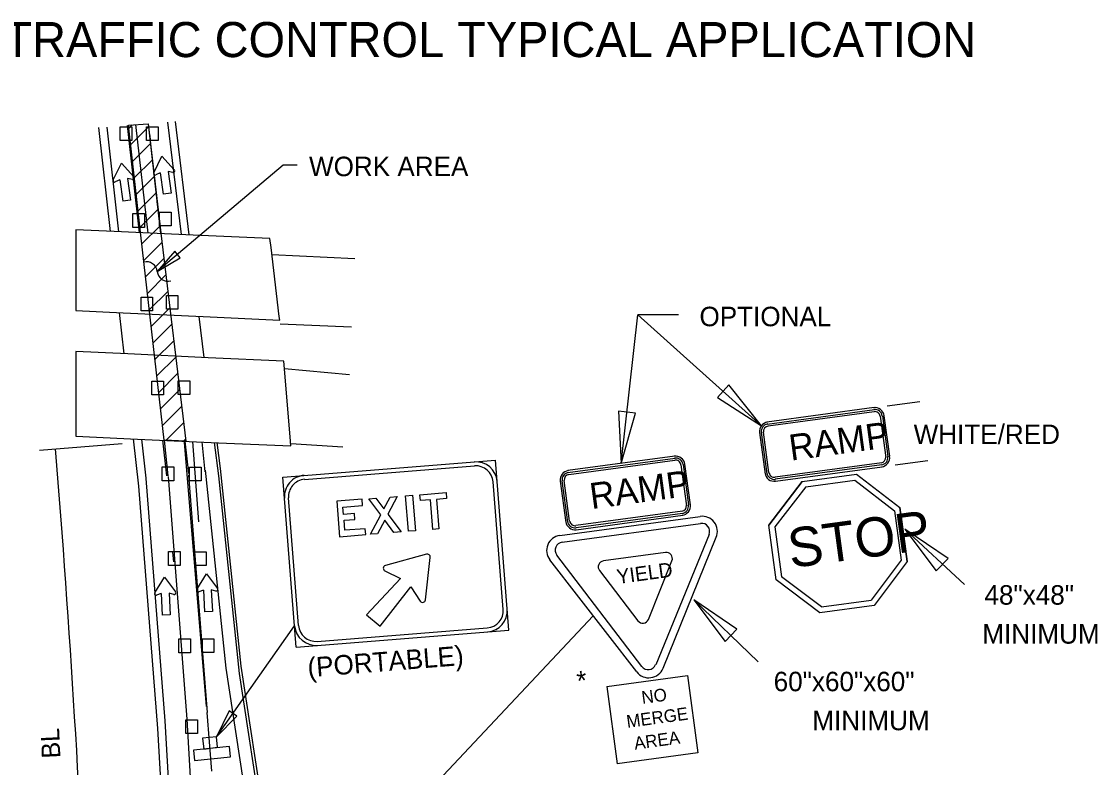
# Model space of a CAD drawing. Extents: x 612.48 to 619.85, y 611.03 to 621.01.
# Drawn here: x 615.025 to 618.336, y 618.714 to 621.01 of the extents above; entities that cross this region are included whole.
import ezdxf

# ---------------------------------------------------------------- set-up
doc = ezdxf.new("R2010")
doc.units = 0
for name, color, linetype in [('DETL-DIMS', 7, 'Continuous'), ('DETL-LINE', 7, 'Continuous'), ('DETL-NOTE', 7, 'Continuous'), ('DETL-TITL', 7, 'Continuous'), ('USER-BORD', 7, 'Continuous')]:
    doc.layers.add(name, color=color, linetype=linetype)

# ---------------------------------------------------------------- blocks, each defined once
blk = doc.blocks.new('SIGN14')
at = {"layer": 'USER-BORD'}
for points in [[(-0.0134, 0.0182), (0.011, 0.0189), (0.011, 0.0371), (-0.0134, 0.0371)], [(-0.0314, 0.0182), (-0.0314, 0), (0.032, 0), (0.032, 0.0182)]]:
    blk.add_lwpolyline(points, close=True, dxfattribs=at)

msp = doc.modelspace()

# ---------------------------------------------------------------- linework, layer by layer
at = {"layer": 'DETL-DIMS'}
for p, q in [((615.8309, 620.5677), (615.4432, 620.2404)), ((615.8738, 620.5677), (615.8309, 620.5677)), ((616.8708, 619.6502), (616.9221, 620.1071)), ((616.9221, 620.1071), (617.3017, 619.7661)), ((617.0473, 620.1071), (616.9221, 620.1071)), ((617.6888, 619.8271), (617.7898, 619.8408)), ((615.0807, 619.6909), (615.3347, 619.7115)), ((617.7134, 619.6453), (617.814, 619.659)), ((617.7434, 619.4477), (617.9271, 619.277)), ((617.0938, 619.2306), (617.2916, 619.0391)), ((615.9365, 618.2792), (616.7846, 619.1808)), ((615.6254, 618.8084), (615.8656, 619.1504))]:
    msp.add_line(p, q, dxfattribs=at)
for points in [[(615.514, 620.2825), (615.4966, 620.3032), (615.4431, 620.2403)], [(617.202, 619.8918), (617.1666, 619.8527), (617.3017, 619.7661)], [(616.9146, 619.8046), (616.8622, 619.8105), (616.8708, 619.6502)], [(617.8397, 619.3193), (617.8761, 619.3574), (617.7434, 619.4477)], [(617.1902, 619.1023), (617.2266, 619.1404), (617.0938, 619.2306)], [(615.688, 618.872), (615.6639, 618.8889), (615.6254, 618.8084)]]:
    msp.add_lwpolyline(points, close=True, dxfattribs=at)
for centre, radius, start, end in [((615.41, 620.2372), 0.0333, 5.7397, 105.25), ((615.4763, 620.2438), 0.0333, 185.7397, 285.25), ((573.0337, 616.2812), 42.2346, 2.39201, 4.63613)]:
    msp.add_arc(centre, radius, start, end, dxfattribs=at)
at = {"layer": 'DETL-LINE'}
for p, q in [((615.3541, 620.6908), (615.4151, 620.6956)), ((615.3551, 620.6813), (615.3655, 620.6917)), ((615.3609, 620.6305), (615.4162, 620.6858)), ((615.4151, 620.6956), (615.4543, 620.3593)), ((615.3667, 620.5797), (615.4221, 620.6352)), ((615.3077, 620.5232), (615.3328, 620.5739)), ((615.3328, 620.5739), (615.3707, 620.532)), ((615.3724, 620.5289), (615.428, 620.5845)), ((615.4324, 620.5448), (615.4574, 620.5956)), ((615.4574, 620.5956), (615.4954, 620.5536)), ((615.4522, 620.5447), (615.4386, 620.538)), ((615.4522, 620.5447), (615.4617, 620.4786)), ((615.4912, 620.5456), (615.4765, 620.5482)), ((615.4765, 620.5482), (615.4858, 620.4818)), ((615.3275, 620.5231), (615.314, 620.5164)), ((615.3275, 620.5231), (615.3369, 620.457)), ((615.3664, 620.524), (615.3518, 620.5266)), ((615.3518, 620.5266), (615.361, 620.4602)), ((615.3782, 620.4781), (615.4336, 620.5335)), ((615.384, 620.4273), (615.4399, 620.4832)), ((615.4858, 620.4818), (615.4617, 620.4786)), ((615.361, 620.4602), (615.3369, 620.457)), ((615.3897, 620.3765), (615.4458, 620.4325)), ((615.3955, 620.3257), (615.4517, 620.3818)), ((615.4544, 620.3587), (615.5306, 619.7183)), ((615.4013, 620.2749), (615.4577, 620.3313)), ((615.407, 620.2241), (615.4637, 620.2807)), ((615.4128, 620.1733), (615.4697, 620.2302)), ((615.4186, 620.1225), (615.4757, 620.1796)), ((615.3257, 620.1144), (615.34, 619.9875)), ((615.4243, 620.0717), (615.4817, 620.1291)), ((615.4301, 620.0209), (615.4877, 620.0785)), ((615.5712, 620.1026), (615.5867, 619.976)), ((615.4359, 619.9701), (615.4937, 620.0279)), ((615.4416, 619.9193), (615.4997, 619.9774)), ((615.4474, 619.8685), (615.5057, 619.9268)), ((615.4532, 619.8177), (615.5118, 619.8763)), ((615.4589, 619.7669), (615.5178, 619.8257)), ((617.6488, 619.8217), (617.319, 619.7769)), ((617.32, 619.7712), (617.6496, 619.8159)), ((617.3224, 619.7653), (617.6487, 619.8096)), ((615.4697, 619.7211), (615.5238, 619.7751)), ((617.6672, 619.7952), (617.6844, 619.6688)), ((617.6674, 619.7951), (617.6672, 619.7952)), ((617.674, 619.7962), (617.6908, 619.6713)), ((617.6966, 619.6722), (617.6797, 619.7969)), ((617.2962, 619.7448), (617.3134, 619.6175)), ((617.3192, 619.6185), (617.3019, 619.7457)), ((617.3249, 619.6217), (617.308, 619.7464)), ((615.3692, 619.7256), (615.3854, 619.5801)), ((615.3948, 619.7244), (615.4081, 619.6047)), ((615.4596, 619.7215), (615.4719, 619.6118)), ((615.4638, 619.7213), (615.476, 619.6123)), ((615.5238, 619.7186), (615.5299, 619.7247)), ((615.5946, 618.9015), (615.5273, 619.7157)), ((615.5276, 619.7185), (615.5387, 619.6193)), ((615.5512, 619.7174), (615.5704, 619.4703)), ((615.5906, 619.6241), (615.5811, 619.7161)), ((615.6186, 619.7144), (615.6312, 619.6117)), ((615.6267, 619.714), (615.6364, 619.6343)), ((616.0136, 619.7), (615.8538, 619.7103)), ((615.8295, 619.6083), (616.4836, 619.6599)), ((615.8959, 619.6011), (616.4192, 619.6424)), ((616.5249, 619.1366), (616.4836, 619.6599)), ((617.0357, 619.6726), (616.7058, 619.6278)), ((616.7068, 619.622), (617.0364, 619.6667)), ((616.7093, 619.6161), (617.0355, 619.6604)), ((617.054, 619.6461), (617.0712, 619.5196)), ((617.0542, 619.6459), (617.054, 619.6461)), ((617.0607, 619.647), (617.0777, 619.5222)), ((617.0835, 619.523), (617.0666, 619.6478)), ((617.6721, 619.6523), (617.3438, 619.6077)), ((617.6722, 619.6456), (617.3447, 619.6012)), ((615.8708, 619.085), (615.8295, 619.6083)), ((617.3455, 619.5954), (617.6731, 619.6398)), ((617.4271, 619.5942), (617.5948, 619.617)), ((617.4271, 619.5942), (617.5948, 619.617)), ((617.5948, 619.617), (617.7279, 619.5142)), ((617.5948, 619.617), (617.7279, 619.5142)), ((616.5074, 619.201), (616.4764, 619.5935)), ((616.683, 619.5957), (616.7003, 619.4683)), ((616.7061, 619.4694), (616.6887, 619.5965)), ((616.7118, 619.4726), (616.6948, 619.5973)), ((617.4271, 619.5942), (617.325, 619.46)), ((617.325, 619.46), (617.4271, 619.5942)), ((617.4382, 619.5777), (617.3432, 619.4548)), ((617.4382, 619.5777), (617.5896, 619.5982)), ((617.5896, 619.5982), (617.7118, 619.5044)), ((615.878, 619.1514), (615.847, 619.5438)), ((617.7504, 619.3482), (617.7279, 619.5142)), ((617.7279, 619.5142), (617.7504, 619.3482)), ((616.6816, 619.4285), (617.1132, 619.487)), ((617.0589, 619.5031), (616.7306, 619.4586)), ((617.059, 619.4964), (616.7316, 619.452)), ((616.7323, 619.4462), (617.0599, 619.4907)), ((617.7118, 619.5044), (617.7324, 619.3524)), ((616.6886, 619.4076), (617.1146, 619.4655)), ((617.3478, 619.2919), (617.325, 619.46)), ((617.3478, 619.2919), (617.325, 619.46)), ((617.3432, 619.4548), (617.3641, 619.3012)), ((617.1408, 619.4315), (616.9766, 619.0307)), ((616.9992, 619.0196), (617.1632, 619.4228)), ((616.2719, 619.3704), (616.1451, 619.3356)), ((616.2686, 619.2302), (616.2831, 619.3608)), ((616.9184, 619.0085), (616.6508, 619.3531)), ((616.934, 619.0252), (616.6723, 619.3681)), ((617.0068, 619.3759), (616.8159, 619.35)), ((616.9542, 619.1701), (617.0266, 619.3505)), ((617.0068, 619.3759), (617.0068, 619.3759)), ((617.7324, 619.3524), (617.6397, 619.2292)), ((617.7504, 619.3482), (617.6485, 619.2129)), ((617.7504, 619.3482), (617.6485, 619.2129)), ((615.5652, 619.2619), (615.5947, 619.3103)), ((615.5947, 619.3103), (615.6286, 619.265)), ((616.1437, 619.3191), (616.1914, 619.2964)), ((616.8036, 619.3201), (616.9221, 619.1657)), ((615.4353, 619.2514), (615.4648, 619.2998)), ((615.4648, 619.2998), (615.4987, 619.2545)), ((616.1914, 619.2964), (616.087, 619.1846)), ((617.482, 619.1903), (617.3478, 619.2919)), ((617.482, 619.1903), (617.3478, 619.2919)), ((617.4872, 619.2086), (617.3641, 619.3012)), ((615.4549, 619.2496), (615.4409, 619.2442)), ((615.4549, 619.2496), (615.4584, 619.1828)), ((615.4938, 619.2469), (615.4794, 619.2508)), ((615.4794, 619.2508), (615.4826, 619.1839)), ((615.5848, 619.2601), (615.5708, 619.2547)), ((615.5848, 619.2601), (615.5883, 619.1934)), ((615.6237, 619.2574), (615.6092, 619.2614)), ((615.6092, 619.2614), (615.6125, 619.1944)), ((616.1285, 619.1492), (616.2228, 619.27)), ((616.2228, 619.27), (616.2523, 619.2262)), ((617.6485, 619.2129), (617.482, 619.1903)), ((617.6485, 619.2129), (617.482, 619.1903)), ((617.4872, 619.2086), (617.6397, 619.2292)), ((615.4826, 619.1839), (615.4584, 619.1828)), ((615.6125, 619.1944), (615.5883, 619.1934)), ((616.087, 619.1846), (616.1285, 619.1492)), ((615.8708, 619.085), (616.5249, 619.1366)), ((615.9352, 619.1025), (616.4586, 619.1438)), ((616.8258, 618.9638), (617.0742, 618.9976)), ((617.0742, 618.9976), (617.1065, 618.7592)), ((616.8258, 618.9638), (616.8582, 618.7254)), ((615.611, 618.7031), (615.5961, 618.8831)), ((617.1065, 618.7592), (616.8582, 618.7254))]:
    msp.add_line(p, q, dxfattribs=at)
for points in [[(615.4979, 620.7022), (615.5405, 620.3535)], [(615.2622, 620.6836), (615.2979, 620.3641)], [(615.2874, 620.6855), (615.3234, 620.363)], [(615.3883, 620.3601), (615.3514, 620.6906)], [(615.5306, 619.7183), (615.464, 619.7212), (615.3924, 620.353), (615.3541, 620.6908)], [(615.4154, 620.6956), (615.4532, 620.3573)], [(615.4748, 620.7003), (615.517, 620.3545)], [(615.4189, 620.6646), (615.4198, 620.6559)], [(615.4198, 620.6559), (615.4208, 620.6472)], [(615.3624, 620.592), (615.3592, 620.621)], [(615.3656, 620.563), (615.3624, 620.592)], [(615.4266, 620.595), (615.4276, 620.5863)], [(615.4276, 620.5863), (615.4286, 620.5776)], [(615.4344, 620.5255), (615.4354, 620.5168)], [(615.4354, 620.5168), (615.4363, 620.5081)], [(615.4422, 620.456), (615.4431, 620.4472)], [(615.4431, 620.4472), (615.4441, 620.4385)], [(615.3883, 620.3601), (615.3851, 620.3891)], [(615.4499, 620.3864), (615.4509, 620.3777)], [(615.4509, 620.3777), (615.4519, 620.369)], [(615.1921, 620.3688), (615.1921, 620.1208)], [(615.1921, 620.1208), (615.3385, 620.1138), (615.5842, 620.1019), (615.8199, 620.0906), (615.8185, 620.1019), (615.7931, 620.3146), (615.7898, 620.3425), (615.5535, 620.3529), (615.3106, 620.3636), (615.1921, 620.3688)], [(615.1921, 620.3688), (615.1921, 620.1208)], [(615.1921, 620.1208), (615.3385, 620.1138), (615.5842, 620.1019), (615.8198, 620.0906), (615.8185, 620.1019), (615.7931, 620.3146), (615.7898, 620.3425), (615.5535, 620.3529), (615.3106, 620.3636), (615.1921, 620.3688)], [(615.7957, 620.2926), (616.0508, 620.2803)], [(615.8211, 620.08), (616.0407, 620.0704)], [(615.1921, 619.9944), (615.1921, 619.7335)], [(615.1921, 619.7335), (615.3819, 619.725), (615.6316, 619.7138), (615.8543, 619.7038), (615.852, 619.7324), (615.8329, 619.9644), (615.5996, 619.9754), (615.3527, 619.9869), (615.1921, 619.9944)], [(615.8348, 619.9419), (616.0343, 619.9234)], [(615.4763, 619.6094), (615.5343, 618.8629), (615.5704, 618.2397), (615.5826, 617.8624)], [(615.5393, 619.6143), (615.5961, 618.8831)], [(615.59, 619.6294), (615.6541, 619.0199), (615.7271, 618.543), (615.7872, 618.1851), (615.8194, 618.0593)], [(615.6312, 619.6117), (615.6951, 619.0032), (615.7679, 618.5278), (615.8276, 618.1721), (615.8592, 618.0483)], [(615.6312, 619.6117), (615.6951, 619.0032), (615.7679, 618.5278), (615.8276, 618.1721), (615.8592, 618.0483)], [(615.6312, 619.6117), (615.6951, 619.0032), (615.7679, 618.5278), (615.8276, 618.1721), (615.8592, 618.0483)], [(615.6364, 619.6343), (615.7004, 619.0258), (615.7732, 618.5504), (615.8329, 618.1947), (615.8646, 618.0709)], [(615.3854, 619.5801), (615.4434, 618.8345), (615.4793, 618.2132), (615.4908, 617.8594)], [(615.4082, 619.6041), (615.4661, 618.8583), (615.5021, 618.2366), (615.5143, 617.8602)], [(615.4902, 619.3765), (615.4925, 619.3474)]]:
    msp.add_lwpolyline(points, dxfattribs=at)
for points in [[(615.3649, 620.6438), (615.3294, 620.6438), (615.3294, 620.686), (615.3649, 620.686)], [(615.4459, 620.644), (615.4104, 620.644), (615.4104, 620.6862), (615.4459, 620.6862)], [(615.4034, 620.3767), (615.3679, 620.3767), (615.3679, 620.4189), (615.4034, 620.4189)], [(615.4854, 620.381), (615.4499, 620.381), (615.4499, 620.4232), (615.4854, 620.4232)], [(615.4285, 620.1196), (615.393, 620.1196), (615.393, 620.1618), (615.4285, 620.1618)], [(615.5068, 620.1246), (615.4713, 620.1246), (615.4713, 620.1668), (615.5068, 620.1668)], [(615.4618, 619.8615), (615.4263, 619.8615), (615.4263, 619.9037), (615.4618, 619.9037)], [(615.5431, 619.8625), (615.5076, 619.8625), (615.5076, 619.9047), (615.5431, 619.9047)], [(615.4936, 619.597), (615.4581, 619.597), (615.4581, 619.6392), (615.4936, 619.6392)], [(615.5781, 619.596), (615.5426, 619.596), (615.5426, 619.6382), (615.5781, 619.6382)], [(616.1932, 619.4396), (616.1714, 619.4378), (616.143, 619.4757), (616.121, 619.4338), (616.0992, 619.4321), (616.1308, 619.4921), (616.094, 619.5413), (616.1158, 619.543), (616.1403, 619.5102), (616.1594, 619.5465), (616.1812, 619.5482), (616.1526, 619.4938)], [(616.2288, 619.552), (616.2375, 619.443), (616.2156, 619.4413), (616.207, 619.5502)], [(616.309, 619.4487), (616.2912, 619.4472), (616.2841, 619.5381), (616.2528, 619.5356), (616.2513, 619.5538), (616.3317, 619.5601), (616.3332, 619.5419), (616.3018, 619.5394)], [(616.0843, 619.4309), (616.0828, 619.4492), (616.0206, 619.4442), (616.0181, 619.4752), (616.0509, 619.4778), (616.0494, 619.4958), (616.0162, 619.4932), (616.0144, 619.5156), (616.0747, 619.5203), (616.0732, 619.5398), (615.9952, 619.5335), (616.0038, 619.4246)], [(615.5133, 619.3364), (615.4778, 619.3364), (615.4778, 619.3786), (615.5133, 619.3786)], [(615.5938, 619.3356), (615.5582, 619.3356), (615.5582, 619.3778), (615.5938, 619.3778)], [(615.5449, 619.0676), (615.5094, 619.0676), (615.5094, 619.1098), (615.5449, 619.1098)], [(615.6173, 619.0683), (615.5818, 619.0683), (615.5818, 619.1105), (615.6173, 619.1105)], [(615.5664, 618.8192), (615.5309, 618.8192), (615.5309, 618.8614), (615.5664, 618.8614)]]:
    msp.add_lwpolyline(points, close=True, dxfattribs=at)
for centre, radius, start, end in [((615.4366, 620.5425), 0.00481, 153.7202, 295.9805), ((615.492, 620.5503), 0.00481, 259.9805, 42.2408), ((615.3119, 620.5209), 0.00481, 153.7202, 295.9805), ((615.3673, 620.5287), 0.00481, 259.9805, 42.2408), ((615.744, 620.3932), 0.2916, 186.6623, 186.7853), ((617.651, 619.7929), 0.0289, 7.7318, 97.7318), ((617.651, 619.7929), 0.0231, 7.7318, 97.7318), ((617.651, 619.7929), 0.0166, 7.7318, 97.7318), ((617.3247, 619.7486), 0.0289, 97.7318, 187.7318), ((617.3247, 619.7486), 0.0231, 97.7318, 187.7318), ((617.3247, 619.7486), 0.0166, 97.7318, 187.7318), ((616.4233, 619.5893), 0.0656, 4.5131, 94.5131), ((616.4233, 619.5893), 0.0533, 4.5131, 94.5131), ((617.0378, 619.6437), 0.0289, 7.7318, 97.7318), ((617.0378, 619.6437), 0.0231, 7.7318, 97.7318), ((617.0378, 619.6437), 0.0166, 7.7318, 97.7318), ((617.6679, 619.6683), 0.0166, 277.7318, 7.7318), ((617.6679, 619.6683), 0.0231, 277.7318, 7.7318), ((617.6679, 619.6683), 0.0289, 277.7318, 7.7318), ((615.9001, 619.548), 0.0656, 94.5131, 184.5131), ((616.7116, 619.5994), 0.0289, 97.7318, 187.7318), ((616.7116, 619.5994), 0.0231, 97.7318, 187.7318), ((616.7116, 619.5994), 0.0166, 97.7318, 187.7318), ((617.3417, 619.624), 0.0289, 187.7318, 277.7318), ((617.3417, 619.624), 0.0231, 187.7318, 277.7318), ((617.3417, 619.624), 0.0166, 187.7318, 277.7318), ((615.9001, 619.548), 0.0533, 94.5131, 184.5131), ((617.0547, 619.5191), 0.0166, 277.7318, 7.7318), ((617.0547, 619.5191), 0.0231, 277.7318, 7.7318), ((617.0547, 619.5191), 0.0289, 277.7318, 7.7318), ((617.1196, 619.4405), 0.047, 337.862, 97.7318), ((616.7285, 619.4748), 0.0289, 187.7318, 277.7318), ((616.7285, 619.4748), 0.0231, 187.7318, 277.7318), ((616.7285, 619.4748), 0.0166, 187.7318, 277.7318), ((617.118, 619.441), 0.0247, 337.7049, 97.7318), ((616.688, 619.3819), 0.047, 97.7318, 217.83), ((616.6919, 619.3831), 0.0247, 97.7318, 217.3433), ((616.8185, 619.3315), 0.0186, 97.7318, 217.4767), ((617.0094, 619.3575), 0.0186, 338.117, 97.7318), ((615.4392, 619.2488), 0.00481, 148.536, 290.7963), ((615.4951, 619.2515), 0.00481, 254.7963, 37.0566), ((615.5691, 619.2593), 0.00481, 148.536, 290.7963), ((615.625, 619.2621), 0.00481, 254.7963, 37.0566), ((616.4543, 619.1969), 0.0533, 274.5131, 4.5131), ((616.4543, 619.1969), 0.0656, 274.5131, 4.5131), ((615.931, 619.1556), 0.0656, 184.5131, 274.5131), ((615.931, 619.1556), 0.0533, 184.5131, 274.5131), ((616.9369, 619.177), 0.0186, 217.4767, 338.117), ((616.9556, 619.0373), 0.047, 217.83, 337.862), ((616.9536, 619.0401), 0.0247, 217.3433, 337.7049)]:
    msp.add_arc(centre, radius, start, end, dxfattribs=at)
for centre, major_axis, start_param, end_param in [((616.2741, 619.3619), (0.00577, 0.00676), 5.309039, 7.25726), ((616.1474, 619.3272), (-0.00577, -0.00676), 4.115761, 6.547716), ((616.2597, 619.2313), (-0.00577, -0.00676), 6.014153, 8.450659)]:
    msp.add_ellipse(centre, major_axis=major_axis, ratio=0.999987, start_param=start_param, end_param=end_param, dxfattribs=at)
at = {"layer": 'DETL-TITL'}
msp.add_lwpolyline([(615.4148, 620.359), (615.3776, 620.6927)], dxfattribs=at)

# ---------------------------------------------------------------- block references
at = {"layer": 'DETL-LINE', "xscale": 1.760000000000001, "yscale": 1.760000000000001, "rotation": 5.654309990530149}
msp.add_blockref('SIGN14', (615.6126, 618.7415), dxfattribs=at)

# ---------------------------------------------------------------- texts
at = {"layer": 'DETL-LINE'}
for s, height, p in [('RAMP', 0.07987, (617.3925, 619.6584)), ('RAMP', 0.07987, (616.7793, 619.5093)), ('STOP', 0.12086, (617.392, 619.3279)), ('YIELD', 0.04472, (616.8597, 619.2788)), ('NO', 0.03894, (616.9357, 618.9098)), ('MERGE', 0.03894, (616.8893, 618.8361)), ('AREA', 0.03894, (616.9128, 618.7691))]:
    msp.add_text(s, height=height, rotation=7.7318, dxfattribs=at).set_placement(p)
at = {"layer": 'DETL-NOTE'}
for s, p in [('WORK AREA', (615.91, 620.5342)), ('OPTIONAL', (617.1113, 620.0723)), ('WHITE/RED', (617.7703, 619.7098)), ('48"x48"', (617.9882, 619.2154)), ('MINIMUM', (617.9816, 619.0954)), ('60"x60"x60"', (617.3396, 618.9489)), ('MINIMUM', (617.4586, 618.8289))]:
    msp.add_text(s, height=0.06, dxfattribs=at).set_placement(p)
for s, height, rotation, p in [('(PORTABLE)', 0.06, 4.5107, (615.9077, 618.9919)), ('*', 0.06, 7.7318, (616.7383, 618.9499)), ('BL', 0.057, 92.6764, (615.1452, 618.7434))]:
    msp.add_text(s, height=height, rotation=rotation, dxfattribs=at).set_placement(p)
at = {"layer": 'DETL-TITL'}
msp.add_text('TEMPORARY TRAFFIC CONTROL TYPICAL APPLICATION', height=0.108, dxfattribs=at).set_placement((614.0149, 620.9006))

doc.saveas('drawing.dxf')
